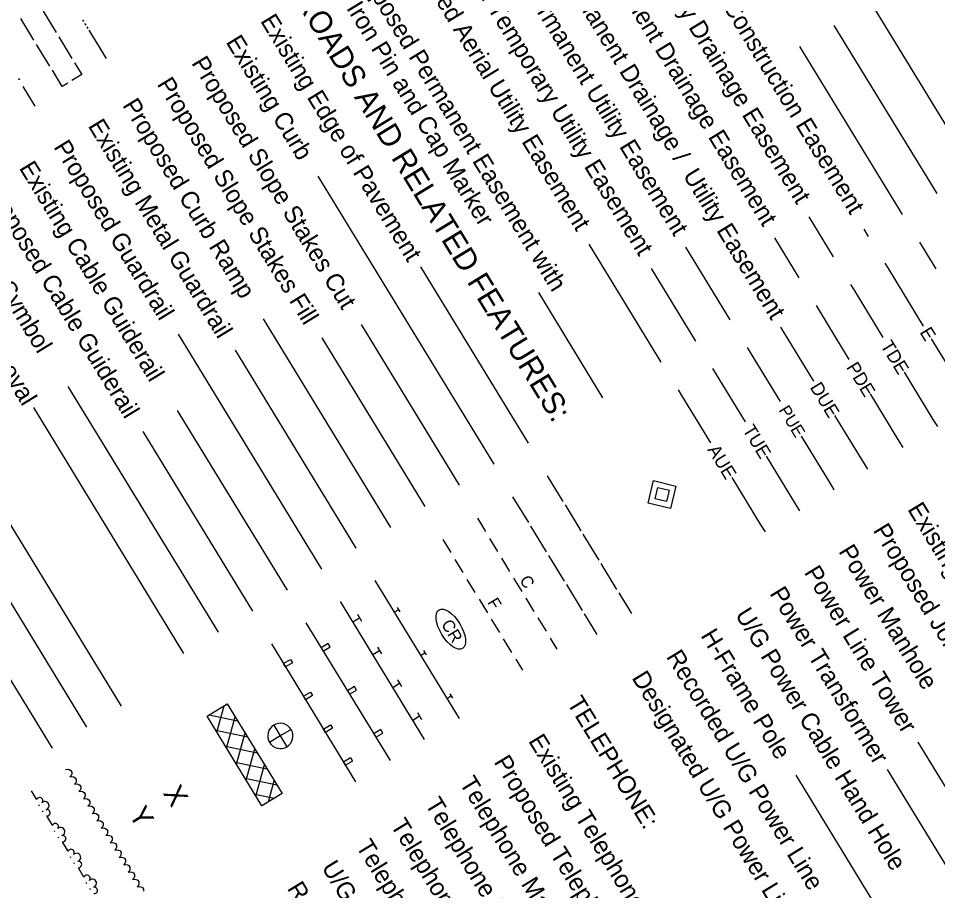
# Model space of a CAD drawing. Extents: x 1750583 to 1791140, y 783580 to 827376.
# Drawn here: x 1755844 to 1760850, y 799616 to 804366 of the extents above; entities that cross this region are included whole.
import ezdxf

# ---------------------------------------------------------------- set-up
doc = ezdxf.new("R2010")
doc.units = 0
for name, color, linetype in [('Prop Easement Permanent Drainage Utility', 7, 'Continuous'), ('Prop ROW Permanent Easement CELL', 7, 'Continuous'), ('Prop WCC CELL', 7, 'Continuous'), ('Sheet Symbology CELL', 7, 'Continuous')]:
    doc.layers.add(name, color=color, linetype=linetype)

msp = doc.modelspace()

# ---------------------------------------------------------------- linework, layer by layer
at = {"layer": 'Prop Easement Permanent Drainage Utility'}
for p, q in [((1759995, 802684.3), (1760174.5, 802390.5)), ((1760289.2, 802202.8), (1760468.2, 801909.9))]:
    msp.add_line(p, q, dxfattribs=at)
at = {"layer": 'Prop ROW Permanent Easement CELL'}
msp.add_line((1759350, 801772.7), (1759350, 801772.7), dxfattribs=at)
for points in [[(1759425.5, 801818.9), (1759396.1, 801697.1), (1759274.4, 801726.5), (1759303.8, 801848.3)], [(1759387.7, 801795.8), (1759373, 801734.9), (1759312.2, 801749.6), (1759326.8, 801810.5)]]:
    msp.add_lwpolyline(points, close=True, dxfattribs=at)
at = {"layer": 'Prop WCC CELL'}
msp.add_ellipse((1758199.1, 801039.6), major_axis=(64.3, -105.3), ratio=0.462467, dxfattribs=at)
at = {"layer": 'Sheet Symbology CELL'}
for p, q in [((1761047.6, 803534.1), (1760488.1, 804449.7)), ((1755977.9, 804405.8), (1756049.6, 804288.5)), ((1755928.8, 804247.2), (1755857.1, 804364.6)), ((1756193.4, 804357.5), (1756199.1, 804348.1)), ((1756204.8, 804338.7), (1756210.6, 804329.3)), ((1756216.3, 804319.9), (1756222.1, 804310.5)), ((1760847.2, 803411.6), (1760287.7, 804327.3)), ((1756227.8, 804301.2), (1756322.3, 804146.5)), ((1756014.8, 804106.4), (1755943.1, 804223.8)), ((1756063.9, 804265), (1756135.6, 804147.7)), ((1760659.4, 803296.9), (1760100, 804212.6)), ((1758434.9, 801937.8), (1757476.3, 803506.7)), ((1760284, 803067.5), (1760151.2, 803284.8)), ((1760473.9, 803178.6), (1760450, 803217.8)), ((1760096.3, 802952.8), (1759963.5, 803170.1)), ((1759345.2, 802494), (1758952.6, 803136.5)), ((1759720.7, 802723.4), (1759479, 803118.9)), ((1760751.4, 803146.5), (1760840.4, 803000.9)), ((1760563.7, 803031.8), (1760578.6, 803007.2)), ((1758622.7, 802052.5), (1758035.7, 803013.2)), ((1759533, 802608.7), (1759291.3, 803004.2)), ((1760578.6, 803007.2), (1760772.2, 802690.4)), ((1760375.9, 802917.1), (1760395.1, 802885.6)), ((1759027.8, 802300), (1758677.9, 802872.6)), ((1760395.1, 802885.6), (1760552.9, 802627.5)), ((1760188.2, 802802.4), (1760210, 802766.7)), ((1760210, 802766.7), (1760367.7, 802508.6)), ((1757871.7, 801593.6), (1757178.2, 802728.7)), ((1758247.2, 801823.1), (1757712.8, 802697.8)), ((1757496.5, 801366.4), (1756715.2, 802645.2)), ((1758059.5, 801708.3), (1757498.9, 802625.8)), ((1760815.2, 802620), (1761008.8, 802303.2)), ((1759812.6, 802572.9), (1759834.7, 802536.9)), ((1757684.2, 801481.1), (1757025.6, 802559)), ((1759834.7, 802536.9), (1759992.4, 802278.7)), ((1759624.9, 802458.2), (1759644.1, 802426.7)), ((1759644.1, 802426.7), (1759801.8, 802168.6)), ((1760667.6, 802439.8), (1760825.3, 802181.6)), ((1756029.2, 800390.8), (1754809.4, 802387.2)), ((1756404.7, 800620.2), (1755365.9, 802320.3)), ((1756933.3, 801022.3), (1756115.3, 802361)), ((1759437.2, 802343.5), (1759456.4, 802312)), ((1760482.4, 802320.8), (1760640.1, 802062.7)), ((1759456.4, 802312), (1759614.1, 802053.9)), ((1756745.6, 800907.6), (1755927.6, 802246.3)), ((1757308.8, 801251.7), (1756710.6, 802230.7)), ((1756216.9, 800505.5), (1755178.2, 802205.6)), ((1760825.3, 802181.6), (1760849.1, 802142.7)), ((1757121, 801137), (1756522.9, 802116)), ((1760107.1, 802091), (1760264.8, 801832.9)), ((1760640.1, 802062.7), (1760661.3, 802028)), ((1759916.5, 801980.9), (1760074.3, 801722.8)), ((1758723.5, 801875.2), (1758809.6, 801734.4)), ((1759728.8, 801866.2), (1759886.5, 801608)), ((1760264.8, 801832.9), (1760285.8, 801798.5)), ((1758535.8, 801760.5), (1758621.8, 801619.7)), ((1758821, 801715.7), (1758907.1, 801574.9)), ((1760074.3, 801722.8), (1760098.1, 801683.8)), ((1758343.6, 801643.1), (1758387.2, 801571.8)), ((1758633.3, 801601), (1758719.3, 801460.2)), ((1759886.5, 801608), (1759910.3, 801569.1)), ((1758155.9, 801528.4), (1758199.5, 801457.1)), ((1758454.3, 801461.9), (1758411, 801532.8)), ((1758918.5, 801556.1), (1759004.6, 801415.3)), ((1758266.6, 801347.2), (1758223.3, 801418.1)), ((1758520.3, 801354), (1758476.7, 801425.3)), ((1758730.8, 801441.4), (1758816.8, 801300.6)), ((1759016, 801396.5), (1759102.1, 801255.7)), ((1758587.7, 801243.7), (1758542.9, 801316.9)), ((1757785.1, 801303.9), (1758243.9, 800552.9)), ((1758332.5, 801239.3), (1758289, 801310.6)), ((1758828.3, 801281.8), (1758914.3, 801141)), ((1759113.5, 801236.9), (1759182.4, 801124.3)), ((1758056.2, 800438.2), (1757597.4, 801189.2)), ((1758399.9, 801129), (1758355.2, 801202.2)), ((1758653.3, 801136.2), (1758608.9, 801209)), ((1757690.2, 801120.5), (1757713.2, 801083)), ((1757890.6, 801131.3), (1757914, 801145.6)), ((1757906.9, 801157.3), (1757921.2, 801133.9)), ((1758925.8, 801122.2), (1758994.6, 801009.6)), ((1757409.7, 801074.5), (1757868.5, 800323.5)), ((1757664.6, 801079.1), (1757701.7, 801101.8)), ((1758465.6, 801021.5), (1758421.1, 801094.3)), ((1758719.6, 801027.8), (1758674.5, 801101.5)), ((1758531.8, 800913.1), (1758486.8, 800986.8)), ((1758778.6, 800931.1), (1758741.9, 800991.2)), ((1757221.9, 800959.8), (1757680.7, 800208.8)), ((1757773.6, 800900.8), (1757810.7, 800923.4)), ((1757799.2, 800942.2), (1757822.1, 800904.6)), ((1758050.3, 800922.7), (1758064.6, 800899.2)), ((1758034, 800896.6), (1758057.4, 800910.9)), ((1758590.9, 800816.4), (1758554.2, 800876.5)), ((1757908.2, 800763.8), (1757931.1, 800726.3)), ((1757882.6, 800722.4), (1757919.6, 800745.1)), ((1758177.3, 800661.9), (1758200.8, 800676.3)), ((1758193.6, 800688), (1758208, 800664.5)), ((1756871.7, 800565.9), (1756981.5, 800633)), ((1756924.7, 800479.1), (1756964.6, 800622.7)), ((1756975.9, 800629.6), (1756984.7, 800627.9)), ((1756981.5, 800633), (1757280.3, 800144)), ((1757170.5, 800076.9), (1756871.7, 800565.9)), ((1756882.5, 800572.5), (1757038, 800540.6)), ((1757991.5, 800544.1), (1758028.6, 800566.7)), ((1758017.1, 800585.5), (1758040.1, 800548)), ((1756978.1, 800391.8), (1757024.8, 800562.2)), ((1757234.7, 800516.7), (1757270.5, 800458)), ((1756918.4, 800489.4), (1757091.3, 800453.3)), ((1757031.1, 800305), (1757078.1, 800474.9)), ((1757329.2, 800493.9), (1757270.5, 800458)), ((1757270.5, 800458), (1757211.8, 800422.2)), ((1757270.5, 800458), (1757306.4, 800399.4)), ((1761583.9, 799049.3), (1760743.7, 800424.4)), ((1756971.5, 800402.6), (1757144.7, 800366)), ((1757084.4, 800217.7), (1757131.2, 800388)), ((1757024.8, 800315.3), (1757197.7, 800279.2)), ((1756100.3, 800274.4), (1756110.9, 800277.1)), ((1756110.9, 800277.1), (1756120.5, 800275.2)), ((1756120.5, 800275.2), (1756129.3, 800270.2)), ((1756129.3, 800270.2), (1756134.7, 800261.3)), ((1757137.8, 800130.4), (1757184.2, 800301.2)), ((1761396.2, 798934.5), (1760576.6, 800275.9)), ((1756124.7, 800234.5), (1756135.3, 800237.2)), ((1756131.7, 800242), (1756124.8, 800235.3)), ((1756134.6, 800250.9), (1756131.7, 800242)), ((1756134.7, 800261.3), (1756134.6, 800250.9)), ((1756135.3, 800237.2), (1756144.8, 800235.3)), ((1756144.8, 800235.3), (1756153.7, 800230.3)), ((1756153.7, 800230.3), (1756159.1, 800221.4)), ((1756159.1, 800221.4), (1756159, 800211)), ((1757078.1, 800228), (1757250.8, 800192.3)), ((1757205.7, 800098.4), (1757237.6, 800213.9)), ((1761020.7, 798705.1), (1760080.7, 800243.6)), ((1756149, 800194.6), (1756159.7, 800197.3)), ((1756156, 800202.2), (1756149.2, 800195.4)), ((1756159, 800211), (1756156, 800202.2)), ((1756159.7, 800197.3), (1756169.2, 800195.4)), ((1756169.2, 800195.4), (1756178, 800190.4)), ((1756178, 800190.4), (1756183.5, 800181.5)), ((1756183.4, 800171.2), (1756180.4, 800162.3)), ((1756183.5, 800181.5), (1756183.4, 800171.2)), ((1755912.6, 800159.7), (1755941.2, 800112.8)), ((1756173.4, 800154.8), (1756184, 800157.4)), ((1756180.4, 800162.3), (1756173.6, 800155.5)), ((1756184, 800157.4), (1756193.6, 800155.5)), ((1756193.6, 800155.5), (1756202.4, 800150.6)), ((1756197.8, 800114.9), (1756208.4, 800117.5)), ((1756204.8, 800122.4), (1756198, 800115.6)), ((1756202.4, 800150.6), (1756207.8, 800141.6)), ((1756207.7, 800131.3), (1756204.8, 800122.4)), ((1756207.8, 800141.6), (1756207.7, 800131.3)), ((1756208.4, 800117.5), (1756218, 800115.6)), ((1756218, 800115.6), (1756226.8, 800110.7)), ((1757131.2, 800141.2), (1757239, 800118.8)), ((1757280.3, 800144), (1757170.5, 800076.9)), ((1755953.5, 800082.2), (1755956.3, 800077.5)), ((1756222.2, 800075), (1756232.8, 800077.6)), ((1756229.2, 800082.5), (1756222.3, 800075.7)), ((1756226.8, 800110.7), (1756232.2, 800101.7)), ((1756232.1, 800091.4), (1756229.2, 800082.5)), ((1756232.2, 800101.7), (1756232.1, 800091.4)), ((1756232.8, 800077.6), (1756242.3, 800075.7)), ((1756242.3, 800075.7), (1756251.1, 800070.8)), ((1756251.1, 800070.8), (1756256.6, 800061.8)), ((1755973.5, 800049.4), (1755976.4, 800044.7)), ((1755998.6, 800018.9), (1756027.3, 799972)), ((1756246.5, 800035.1), (1756257.2, 800037.7)), ((1756253.5, 800042.6), (1756246.7, 800035.8)), ((1756256.5, 800051.5), (1756253.5, 800042.6)), ((1756256.6, 800061.8), (1756256.5, 800051.5)), ((1756257.2, 800037.7), (1756266.7, 800035.8)), ((1756266.7, 800035.8), (1756275.5, 800030.9)), ((1756275.5, 800030.9), (1756281, 800022)), ((1756281, 800022), (1756280.9, 800011.6)), ((1756270.9, 799995.2), (1756281.5, 799997.8)), ((1756277.9, 800002.7), (1756271.1, 799995.9)), ((1756280.9, 800011.6), (1756277.9, 800002.7)), ((1756281.5, 799997.8), (1756291.1, 799995.9)), ((1756291.1, 799995.9), (1756299.9, 799991)), ((1756302.3, 799962.8), (1756295.5, 799956)), ((1756299.9, 799991), (1756305.3, 799982.1)), ((1756305.2, 799971.7), (1756302.3, 799962.8)), ((1756305.3, 799982.1), (1756305.2, 799971.7)), ((1756039.5, 799941.4), (1756042.3, 799936.7)), ((1756295.3, 799955.3), (1756305.9, 799957.9)), ((1756305.9, 799957.9), (1756315.5, 799956)), ((1756315.5, 799956), (1756324.3, 799951.1)), ((1756319.7, 799915.4), (1756330.3, 799918)), ((1756326.7, 799922.9), (1756319.8, 799916.2)), ((1756324.3, 799951.1), (1756329.7, 799942.2)), ((1756329.6, 799931.8), (1756326.7, 799922.9)), ((1756329.7, 799942.2), (1756329.6, 799931.8)), ((1756330.3, 799918), (1756339.8, 799916.1)), ((1756339.8, 799916.1), (1756348.6, 799911.2)), ((1756059.6, 799908.6), (1756062.4, 799903.9)), ((1756084.6, 799878.1), (1756113.3, 799831.2)), ((1756344, 799875.5), (1756354.7, 799878.1)), ((1756351, 799883), (1756344.2, 799876.3)), ((1756348.6, 799911.2), (1756354.1, 799902.3)), ((1756354, 799891.9), (1756351, 799883)), ((1756354.1, 799902.3), (1756354, 799891.9)), ((1756354.7, 799878.1), (1756364.2, 799876.2)), ((1756364.2, 799876.2), (1756373, 799871.3)), ((1756373, 799871.3), (1756378.5, 799862.4)), ((1756378.5, 799862.4), (1756378.4, 799852)), ((1756368.4, 799835.6), (1756379, 799838.2)), ((1756375.4, 799843.1), (1756368.6, 799836.4)), ((1756378.4, 799852), (1756375.4, 799843.1)), ((1756379, 799838.2), (1756388.6, 799836.3)), ((1756388.6, 799836.3), (1756397.4, 799831.4)), ((1756397.4, 799831.4), (1756402.8, 799822.5)), ((1756402.8, 799822.5), (1756402.7, 799812.1)), ((1756125.5, 799800.6), (1756128.4, 799795.9)), ((1756145.6, 799767.8), (1756148.5, 799763.1)), ((1756392.8, 799795.7), (1756403.4, 799798.3)), ((1756399.8, 799803.2), (1756393, 799796.5)), ((1756402.7, 799812.1), (1756399.8, 799803.2)), ((1756403.4, 799798.3), (1756413, 799796.4)), ((1756413, 799796.4), (1756421.8, 799791.5)), ((1756424.2, 799763.3), (1756417.3, 799756.6)), ((1756421.8, 799791.5), (1756427.2, 799782.6)), ((1756427.1, 799772.2), (1756424.2, 799763.3)), ((1756427.2, 799782.6), (1756427.1, 799772.2)), ((1756170.6, 799737.3), (1756199.3, 799690.4)), ((1756417.2, 799755.8), (1756427.8, 799758.5)), ((1756427.8, 799758.5), (1756437.3, 799756.6)), ((1756437.3, 799756.6), (1756446.1, 799751.6)), ((1756441.5, 799715.9), (1756452.2, 799718.6)), ((1756448.5, 799723.4), (1756441.7, 799716.7)), ((1756446.1, 799751.6), (1756451.6, 799742.7)), ((1756451.5, 799732.3), (1756448.5, 799723.4)), ((1756451.6, 799742.7), (1756451.5, 799732.3)), ((1756452.2, 799718.6), (1756461.7, 799716.7)), ((1756461.7, 799716.7), (1756470.5, 799711.7)), ((1756465.9, 799676), (1756476.5, 799678.7)), ((1756472.9, 799683.5), (1756466.1, 799676.8)), ((1756470.5, 799711.7), (1756476, 799702.8)), ((1756475.9, 799692.4), (1756472.9, 799683.5)), ((1756476, 799702.8), (1756475.9, 799692.4)), ((1756476.5, 799678.7), (1756486.1, 799676.8)), ((1756486.1, 799676.8), (1756494.9, 799671.8)), ((1756494.9, 799671.8), (1756500.3, 799662.9)), ((1756500.3, 799662.9), (1756500.2, 799652.5)), ((1756211.5, 799659.8), (1756214.4, 799655.1)), ((1756231.6, 799627), (1756234.5, 799622.3)), ((1756490.3, 799636.1), (1756500.9, 799638.8)), ((1756497.3, 799643.7), (1756490.5, 799636.9)), ((1756500.2, 799652.5), (1756497.3, 799643.7)), ((1756500.9, 799638.8), (1756510.5, 799636.9)), ((1756510.5, 799636.9), (1756519.3, 799631.9)), ((1756519.3, 799631.9), (1756524.7, 799623)), ((1756524.7, 799623), (1756524.6, 799612.7))]:
    msp.add_line(p, q, dxfattribs=at)
for points in [[(1756150, 804124.2), (1756189.1, 804060.1), (1756135.8, 804027.6)], [(1756112.4, 804013.3), (1756082.8, 803995.2), (1756029.2, 804083)], [(1755868.2, 803995.1), (1755933.7, 803887.9)]]:
    msp.add_lwpolyline(points, dxfattribs=at)
for points in [[(1757492.7, 800938.6), (1757504.1, 800919.8), (1757541.7, 800942.8), (1757530.2, 800961.5)], [(1757325.2, 800875.1), (1757336.7, 800856.3), (1757299.1, 800833.4), (1757287.7, 800852.2)], [(1757636.1, 800703.9), (1757647.5, 800685.2), (1757685.1, 800708.1), (1757673.6, 800726.9)], [(1757434.2, 800696.8), (1757445.6, 800678), (1757408.1, 800655), (1757396.6, 800673.8)], [(1757543.1, 800518.4), (1757554.6, 800499.6), (1757517.1, 800476.7), (1757505.6, 800495.5)], [(1757779.4, 800469.3), (1757790.9, 800450.5), (1757828.4, 800473.4), (1757817, 800492.2)], [(1757652.1, 800340.1), (1757663.6, 800321.3), (1757626, 800298.4), (1757614.6, 800317.1)]]:
    msp.add_lwpolyline(points, close=True, dxfattribs=at)
for centre, radius, start, end in [((1757270.5, 800458), 68.8, 121.4193, 211.4239), ((1757270.5, 800458), 68.8, 31.4193, 121.4239), ((1757270.5, 800458), 68.8, 301.4193, 31.4239), ((1757270.5, 800458), 68.8, 211.4193, 301.4239), ((1755959.1, 800105), 17.4, 319.8599, 160.6565), ((1755988.5, 800077.9), 22.7, 287.3887, 135.4612), ((1755999.2, 800039.3), 17.4, 262.1934, 102.99), ((1756045.1, 799964.2), 17.4, 319.8599, 160.6565), ((1756074.5, 799937.1), 22.7, 287.3887, 135.4612), ((1756085.2, 799898.5), 17.4, 262.1934, 102.99), ((1756131.1, 799823.4), 17.4, 319.8599, 160.6565), ((1756160.6, 799796.3), 22.7, 287.3887, 135.4612), ((1756171.3, 799757.7), 17.4, 262.1934, 102.99), ((1756217.1, 799682.6), 17.4, 319.8599, 160.6565), ((1756246.6, 799655.5), 22.7, 287.3887, 135.4612), ((1756257.3, 799616.9), 17.4, 262.1934, 102.99)]:
    msp.add_arc(centre, radius, start, end, dxfattribs=at)
msp.add_ellipse((1755847.3, 804035.3), major_axis=(1.85, 1.13), ratio=0.938496, dxfattribs=at)

# ---------------------------------------------------------------- texts
at = {"layer": 'Prop Easement Permanent Drainage Utility'}
msp.add_text('DUE', height=72.05, rotation=301.4249, dxfattribs=at).set_placement((1760152.7, 802356.7))
at = {"layer": 'Prop WCC CELL'}
msp.add_text('CR', height=66, rotation=301.4249, dxfattribs=at).set_placement((1758144.3, 801066.9))
at = {"layer": 'Sheet Symbology CELL'}
for s, height, p in [('Proposed Control of Access Line with', 96.25, (1759908.8, 806032)), ('Proposed Temporary Construction Easement', 96.25, (1759029.6, 805494.8)), ('Proposed Temporary Drainage Easement', 96.25, (1758841.9, 805380.1)), ('Proposed Permanent Drainage Easement', 96.25, (1758654.1, 805265.4)), ('Proposed Permanent Drainage /  Utility Easement', 96.25, (1758460.9, 805147.3)), ('Proposed Permanent Utility Easement', 96.25, (1758278.6, 805035.9)), ('Proposed Temporary Utility Easement', 96.25, (1758090.8, 804921.2)), ('Proposed Aerial Utility Easement', 96.25, (1757903.1, 804806.5)), ('Proposed Permanent Easement with', 96.25, (1757660.4, 804658.2)), ('ROADS AND RELATED FEATURES:', 121, (1757346.8, 804466.6)), ('Iron Pin and Cap Marker', 96.25, (1757627.4, 804422)), ('Existing Edge of Pavement', 96.25, (1757159.1, 804351.9)), ('Existing Curb', 96.25, (1756971.3, 804237.2)), ('Proposed Slope Stakes Cut', 96.25, (1756783.6, 804122.5)), ('Proposed Slope Stakes Fill', 96.25, (1756595.9, 804007.8)), ('Proposed Curb Ramp', 96.25, (1756408.1, 803893.1)), ('Existing Metal Guardrail', 96.25, (1756220.6, 803780.5)), ('Proposed Guardrail', 96.25, (1756033.1, 803665.8)), ('Existing Cable Guiderail', 96.25, (1755845.4, 803551.1)), ('Proposed Cable Guiderail', 96.25, (1755657.6, 803436.4)), ('Equality Symbol', 96.25, (1755469.9, 803321.7)), ('Pavement Removal', 96.25, (1755282.2, 803207)), ('E', 72, (1760750.4, 802656.5)), ('TDE', 72.05, (1760536.8, 802584.2)), ('PDE', 72.05, (1760351.1, 802466.2)), ('PUE', 66, (1759982, 802232.4)), ('TUE', 72.05, (1759785.7, 802125.5)), ('AUE', 72.05, (1759594.2, 802016.9)), ('Existing Joint Use Pole', 96.25, (1760683.8, 801692.8)), ('Proposed Joint Use Pole', 96.25, (1760496, 801577.9)), ('Power Manhole', 96.25, (1760308.3, 801463.2)), ('Power Line Tower', 96.25, (1760120.7, 801348.6)), ('C', 65.2, (1758571, 801307.6)), ('Power Transformer', 96.25, (1759932.9, 801234)), ('F', 65.2, (1758396, 801185.3)), ('U/G Power Cable Hand Hole', 96.25, (1759745.2, 801119)), ('H-Frame Pole', 96.25, (1759557.5, 801004.3)), ('Recorded U/G Power Line', 96.25, (1759369.7, 800889.6)), ('Designated U/G Power Line (S.U.E.*)', 96.25, (1759182.2, 800774.8)), ('TELEPHONE:', 96.25, (1758829.7, 800637.8)), ('Existing Telephone Pole', 96.25, (1758618.8, 800430.8)), ('Proposed Telephone Pole', 96.25, (1758431.1, 800316.1)), ('Telephone Manhole', 96.25, (1758243.3, 800201.4)), ('X', 110, (1756629.5, 800146.6)), ('Telephone Booth', 96.25, (1758055.6, 800086.7)), ('Y', 110, (1756441.8, 800031.9)), ('Telephone Pedestal', 96.25, (1757867.9, 799971.9)), ('Telephone Cell Tower', 96.25, (1757680.2, 799857.1)), ('U/G Telephone Cable Hand Hole', 96.25, (1757492.5, 799742.4)), ('Recorded U/G Telephone Cable', 96.25, (1757304.7, 799627.7))]:
    msp.add_text(s, height=height, rotation=301.4249, dxfattribs=at).set_placement(p)

doc.saveas('drawing.dxf')
